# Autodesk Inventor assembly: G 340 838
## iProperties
Created: 2006-06
Part Number: G 340 838
Document SubType Name: Assembly
Designer: I.Baliuc
Manufacturer: Standard
Standards Organization: Custom
Description: DC - Hauptkontakt
Mass: 280.188 g
Surface Area: 111.402 cm^2
Volume: 31.2658 cm^3
Density: 8.9615 g/cm^3
Title: DC - Hauptkontakt
Company: Mayer & Müller AG Schaltgeräte
Zweck: für  HSLT / mitte
Author: T.Messerschmitt
Revision Number: 340838
